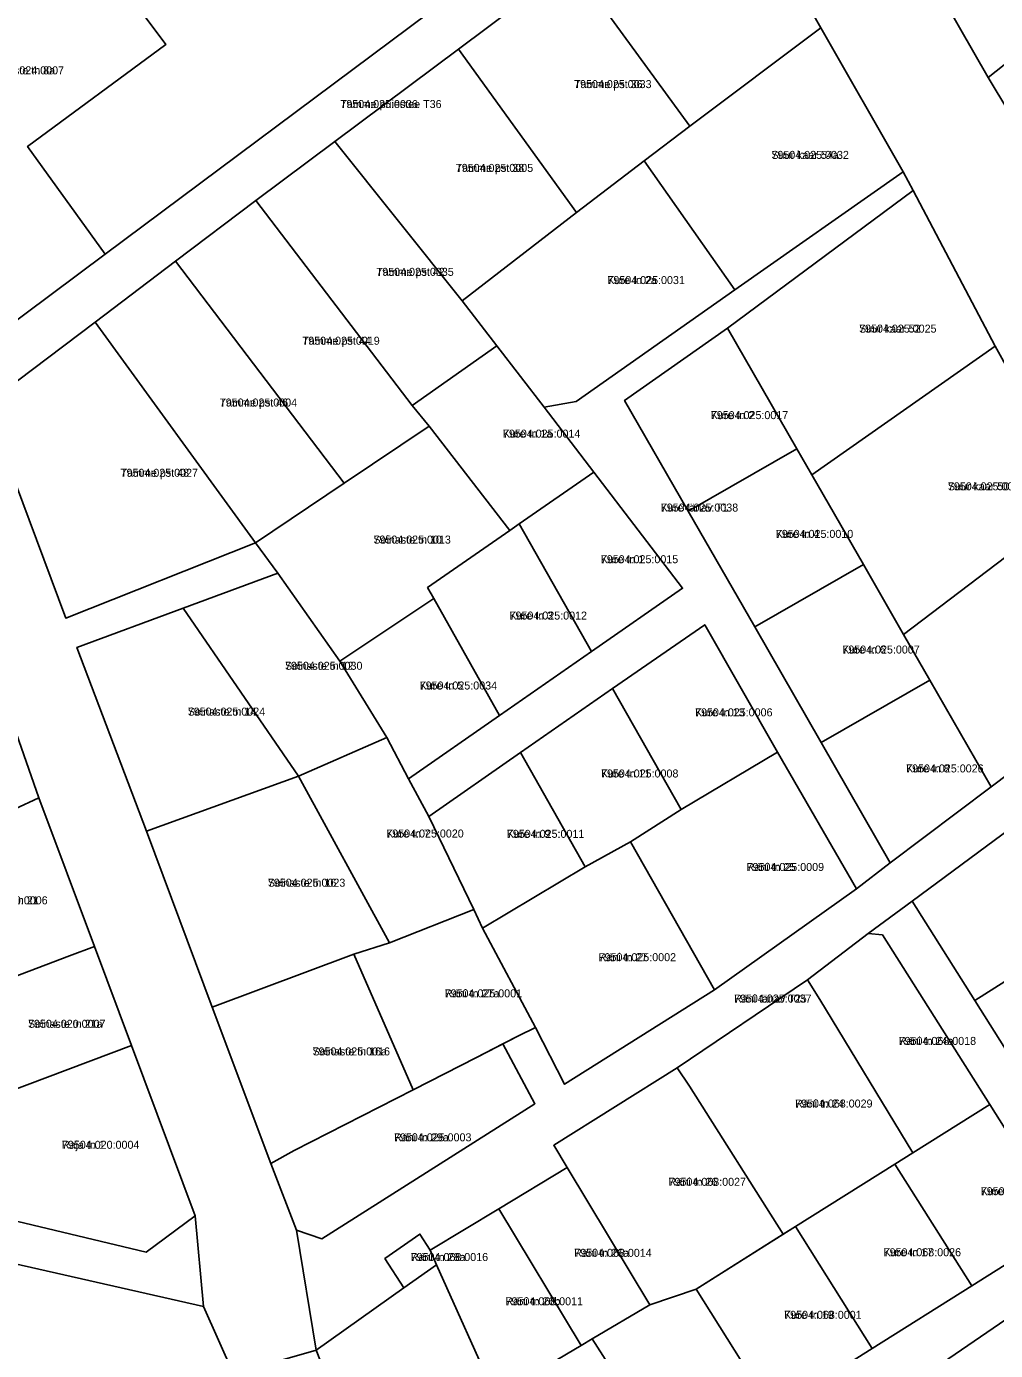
# Model space of a CAD drawing. Extents: x 643847 to 663718, y 6468443 to 6482775.
# Drawn here: x 658107 to 658288.5, y 6471992.7 to 6472240.8 of the extents above; entities that cross this region are included whole.
import ezdxf

# ---------------------------------------------------------------- set-up
doc = ezdxf.new("R2010")
doc.units = 0
for name, color, linetype in [('L_AADRESS', 7, 'Continuous'), ('PIIR', 7, 'Continuous'), ('TUNNUS', 7, 'Continuous')]:
    doc.layers.add(name, color=color, linetype=linetype)

msp = doc.modelspace()

# ---------------------------------------------------------------- linework, layer by layer
at = {"layer": 'PIIR'}
for points in [[(658324.3, 6472260.73), (658287.19, 6472231.24), (658255.18, 6472287.1), (658292.14, 6472314.34), (658310.38, 6472291.08), (658312.11, 6472278.46)], [(658096.55, 6472179.3), (658060.13, 6472228.1), (658085.61, 6472247.27), (658074.4, 6472263.34), (658118.46, 6472296.24), (658129.72, 6472280.2), (658139, 6472266.96), (658121.03, 6472253.66), (658133.15, 6472237.45), (658107.24, 6472218.32), (658121.79, 6472198.16)], [(658158.39, 6472272.98), (658182.38, 6472243.36), (658121.79, 6472198.16), (658107.24, 6472218.32), (658133.15, 6472237.45), (658121.03, 6472253.66), (658139, 6472266.96), (658129.72, 6472280.2), (658143.16, 6472291.75)], [(658209.21, 6472252.47), (658187.94, 6472236.55), (658164.81, 6472219.24), (658149.97, 6472208.2), (658134.95, 6472196.81), (658119.9, 6472185.37), (658099.41, 6472169.96), (658096.55, 6472179.3), (658121.79, 6472198.16), (658182.38, 6472243.36), (658232.79, 6472281.08), (658237.08, 6472273.31)], [(658209.21, 6472252.47), (658237.08, 6472273.31), (658255.85, 6472240.53), (658231.28, 6472222.13)], [(658187.94, 6472236.55), (658209.21, 6472252.47), (658231.28, 6472222.13), (658222.76, 6472215.62), (658210.07, 6472205.97)], [(658255.85, 6472240.53), (658271.27, 6472213.59), (658239.74, 6472191.45), (658222.76, 6472215.62), (658231.28, 6472222.13)], [(658187.94, 6472236.55), (658210.07, 6472205.97), (658188.66, 6472189.39), (658164.81, 6472219.24)], [(658149.97, 6472208.2), (658164.81, 6472219.24), (658188.66, 6472189.39), (658195.15, 6472180.94), (658179.28, 6472169.79)], [(658239.74, 6472191.45), (658209.98, 6472170.55), (658203.97, 6472169.43), (658195.15, 6472180.94), (658188.66, 6472189.39), (658210.07, 6472205.97), (658222.76, 6472215.62)], [(658271.27, 6472213.59), (658273.12, 6472210.07), (658238.37, 6472184.29), (658219.07, 6472170.73), (658230.99, 6472149.95), (658243.43, 6472128.27), (658255.87, 6472106.59), (658268.81, 6472084.03), (658262.48, 6472079.19), (658247.72, 6472104.8), (658234.07, 6472128.69), (658216.83, 6472116.7), (658199.59, 6472104.71), (658182.39, 6472092.74), (658178.57, 6472099.78), (658195.66, 6472111.68), (658212.88, 6472123.66), (658229.92, 6472135.52), (658213.28, 6472157.3), (658203.97, 6472169.43), (658209.98, 6472170.55), (658239.74, 6472191.45)], [(658288.46, 6472180.88), (658254.14, 6472156.79), (658251.35, 6472161.65), (658238.37, 6472184.29), (658273.12, 6472210.07)], [(658149.97, 6472208.2), (658179.28, 6472169.79), (658182.45, 6472165.92), (658166.56, 6472155.23), (658134.95, 6472196.81)], [(658166.56, 6472155.23), (658149.92, 6472144.03), (658119.9, 6472185.37), (658134.95, 6472196.81)], [(658119.9, 6472185.37), (658149.92, 6472144.03), (658114.38, 6472129.94), (658099.41, 6472169.96)], [(658219.07, 6472170.73), (658238.37, 6472184.29), (658251.35, 6472161.65), (658230.99, 6472149.95)], [(658199.29, 6472147.57), (658197.57, 6472146.37), (658182.45, 6472165.92), (658179.28, 6472169.79), (658195.15, 6472180.94), (658203.97, 6472169.43), (658213.28, 6472157.3)], [(658304.45, 6472152.02), (658271.32, 6472126.85), (658263.79, 6472139.96), (658254.14, 6472156.79), (658288.46, 6472180.88)], [(658166.56, 6472155.23), (658182.45, 6472165.92), (658197.57, 6472146.37), (658182.15, 6472135.63), (658183.31, 6472133.58), (658165.71, 6472121.86), (658154.14, 6472138.34), (658149.92, 6472144.03)], [(658230.99, 6472149.95), (658251.35, 6472161.65), (658254.14, 6472156.79), (658263.79, 6472139.96), (658243.43, 6472128.27)], [(658212.88, 6472123.66), (658199.29, 6472147.57), (658213.28, 6472157.3), (658229.92, 6472135.52)], [(658320.52, 6472123.03), (658287.73, 6472098.27), (658276.26, 6472118.28), (658271.32, 6472126.85), (658304.45, 6472152.02)], [(658195.66, 6472111.68), (658183.31, 6472133.58), (658182.15, 6472135.63), (658197.57, 6472146.37), (658199.29, 6472147.57), (658212.88, 6472123.66)], [(658243.43, 6472128.27), (658263.79, 6472139.96), (658271.32, 6472126.85), (658276.26, 6472118.28), (658255.87, 6472106.59)], [(658136.36, 6472131.77), (658154.14, 6472138.34), (658165.71, 6472121.86), (658174.56, 6472107.53), (658158.01, 6472100.31)], [(658195.66, 6472111.68), (658178.57, 6472099.78), (658174.56, 6472107.53), (658165.71, 6472121.86), (658183.31, 6472133.58)], [(658116.47, 6472124.42), (658136.36, 6472131.77), (658158.01, 6472100.31), (658129.49, 6472090.01)], [(658234.07, 6472128.69), (658247.72, 6472104.8), (658229.69, 6472094.04), (658216.83, 6472116.7)], [(658255.87, 6472106.59), (658276.26, 6472118.28), (658287.73, 6472098.27), (658268.81, 6472084.03)], [(658109.36, 6472096.21), (658104.82, 6472094.11), (658081.47, 6472083.26), (658078.38, 6472087.25), (658071.32, 6472096.58), (658102.78, 6472115.07)], [(658216.83, 6472116.7), (658229.69, 6472094.04), (658220.19, 6472087.98), (658211.66, 6472083.29), (658199.59, 6472104.71)], [(658174.56, 6472107.53), (658178.57, 6472099.78), (658182.39, 6472092.74), (658190.85, 6472075.29), (658175.01, 6472069.07), (658158.01, 6472100.31)], [(658235.92, 6472060.26), (658220.19, 6472087.98), (658229.69, 6472094.04), (658247.72, 6472104.8), (658262.48, 6472079.19)], [(658182.39, 6472092.74), (658199.59, 6472104.71), (658211.66, 6472083.29), (658192.47, 6472071.84), (658190.85, 6472075.29)], [(658168.36, 6472066.92), (658141.79, 6472057.03), (658129.49, 6472090.01), (658158.01, 6472100.31), (658175.01, 6472069.07)], [(658119.79, 6472068.36), (658115.12, 6472066.6), (658087.94, 6472056.34), (658085.28, 6472063.98), (658074.69, 6472078.27), (658081.47, 6472083.26), (658104.82, 6472094.11), (658109.36, 6472096.21)], [(658272.91, 6472076.89), (658291.41, 6472090.56), (658304.11, 6472070.54), (658284.64, 6472058.28)], [(658207.83, 6472042.55), (658202.35, 6472053.19), (658192.47, 6472071.84), (658211.66, 6472083.29), (658220.19, 6472087.98), (658235.92, 6472060.26)], [(658199.22, 6472051.61), (658191.3, 6472047.59), (658179.45, 6472041.53), (658168.36, 6472066.92), (658175.01, 6472069.07), (658190.85, 6472075.29), (658192.47, 6472071.84), (658202.35, 6472053.19)], [(658264.68, 6472070.81), (658267.37, 6472070.53), (658287.46, 6472038.78), (658273.07, 6472029.73), (658255.61, 6472058.41), (658253.34, 6472062.14)], [(658296.89, 6472038.82), (658284.64, 6472058.28), (658304.11, 6472070.54), (658310.39, 6472060.55), (658316.36, 6472051.07)], [(658126.71, 6472049.81), (658095.19, 6472037.92), (658087.94, 6472056.34), (658115.12, 6472066.6), (658119.79, 6472068.36)], [(658141.79, 6472057.03), (658168.36, 6472066.92), (658179.45, 6472041.53), (658157.19, 6472030.12), (658152.8, 6472027.71)], [(658228.93, 6472045.66), (658253.34, 6472062.14), (658255.61, 6472058.41), (658273.07, 6472029.73), (658269.69, 6472027.6), (658251.08, 6472015.88), (658248.79, 6472014.43), (658231.24, 6472042.19)], [(658095.19, 6472037.92), (658126.71, 6472049.81), (658138.64, 6472017.87), (658129.48, 6472011.11), (658091.01, 6472020.27)], [(658157.6, 6472015.18), (658152.8, 6472027.71), (658157.19, 6472030.12), (658179.45, 6472041.53), (658191.3, 6472047.59), (658196.25, 6472050.11), (658202.28, 6472038.89), (658162.36, 6472013.6)], [(658228.93, 6472045.66), (658231.24, 6472042.19), (658248.79, 6472014.43), (658232.47, 6472004.15), (658223.81, 6472001.23), (658208.33, 6472026.94), (658205.81, 6472031.13)], [(658284.08, 6472004.75), (658269.69, 6472027.6), (658273.07, 6472029.73), (658287.46, 6472038.78), (658301.84, 6472015.94)], [(658208.33, 6472026.94), (658223.81, 6472001.23), (658212.96, 6471994.81), (658210.9, 6471993.59), (658195.48, 6472019.19)], [(658265.46, 6471993.03), (658251.08, 6472015.88), (658269.69, 6472027.6), (658284.08, 6472004.75)], [(658195.48, 6472019.19), (658210.9, 6471993.59), (658194.89, 6471984.1), (658183.85, 6472008.74), (658182.63, 6472011.46)], [(658246.85, 6471981.3), (658232.47, 6472004.15), (658251.08, 6472015.88), (658265.46, 6471993.03)], [(658180.74, 6472014.47), (658182.63, 6472011.46), (658183.85, 6472008.74), (658177.7, 6472004.37), (658174.17, 6472009.87)], [(658140.18, 6472000.92), (658145.84, 6471988.27), (658108.85, 6471960.72), (658098.74, 6471984.59), (658098.56, 6472010.33)], [(658161.28, 6471992.71), (658177.7, 6472004.37), (658183.85, 6472008.74), (658194.89, 6471984.1), (658198.54, 6471975.94), (658172.4, 6471964.51)], [(658277.4, 6471989.53), (658306.11, 6472009.17), (658315.36, 6471997.27), (658323.4, 6471987.19), (658299.95, 6471970.14), (658295.95, 6471967.23)], [(658228.09, 6471971.22), (658212.96, 6471994.81), (658223.81, 6472001.23), (658232.47, 6472004.15), (658246.85, 6471981.3)], [(658208.99, 6471960.94), (658198.54, 6471975.94), (658194.89, 6471984.1), (658210.9, 6471993.59), (658212.96, 6471994.81), (658228.09, 6471971.22)]]:
    msp.add_lwpolyline(points, close=True, dxfattribs=at)
for points in [[(658255.18, 6472287.1), (658287.19, 6472231.24), (658291.01, 6472224.8)], [(658304.45, 6472152.02), (658288.46, 6472180.88), (658273.12, 6472210.07), (658271.27, 6472213.59), (658255.85, 6472240.53), (658237.08, 6472273.31)], [(658333.8, 6472258.8), (658305.91, 6472236.61), (658291.01, 6472224.8), (658287.19, 6472231.24), (658324.3, 6472260.73)], [(658099.41, 6472169.96), (658114.38, 6472129.94), (658149.92, 6472144.03), (658154.14, 6472138.34), (658136.36, 6472131.77), (658116.47, 6472124.42), (658129.49, 6472090.01), (658141.79, 6472057.03), (658152.8, 6472027.71), (658157.6, 6472015.18), (658161.28, 6471992.71), (658145.84, 6471988.27), (658140.18, 6472000.92), (658138.64, 6472017.87), (658126.71, 6472049.81), (658119.79, 6472068.36), (658109.36, 6472096.21), (658102.78, 6472115.07)], [(658291.41, 6472090.56), (658272.91, 6472076.89), (658264.68, 6472070.81), (658253.34, 6472062.14), (658228.93, 6472045.66), (658205.81, 6472031.13), (658208.33, 6472026.94), (658195.48, 6472019.19), (658182.63, 6472011.46), (658180.74, 6472014.47), (658174.17, 6472009.87), (658177.7, 6472004.37), (658161.28, 6471992.71), (658157.6, 6472015.18), (658162.36, 6472013.6), (658202.28, 6472038.89), (658196.25, 6472050.11), (658199.22, 6472051.61), (658202.35, 6472053.19), (658207.83, 6472042.55), (658235.92, 6472060.26), (658262.48, 6472079.19), (658268.81, 6472084.03), (658287.73, 6472098.27), (658320.52, 6472123.03)], [(658246.85, 6471981.3), (658265.46, 6471993.03), (658284.08, 6472004.75), (658301.84, 6472015.94), (658287.46, 6472038.78), (658267.37, 6472070.53), (658264.68, 6472070.81), (658272.91, 6472076.89), (658284.64, 6472058.28), (658296.89, 6472038.82), (658308.61, 6472020.2), (658320.86, 6472000.73), (658315.36, 6471997.27), (658306.11, 6472009.17), (658277.4, 6471989.53)], [(658091.01, 6472020.27), (658129.48, 6472011.11), (658138.64, 6472017.87), (658140.18, 6472000.92), (658098.56, 6472010.33)], [(658145.84, 6471988.27), (658161.28, 6471992.71), (658172.4, 6471964.51)]]:
    msp.add_lwpolyline(points, dxfattribs=at)

# ---------------------------------------------------------------- texts
at = {"layer": 'L_AADRESS'}
for s, p in [('Soinaste tn 8a', (658099.57, 6472231.84)), ('Tamme pst 36', (658209.61, 6472229.26)), ('Tamme puiestee T36', (658165.83, 6472225.52)), ('Suur kaar 54a', (658246.57, 6472215.99)), ('Tamme pst 38', (658187.44, 6472213.55)), ('Tamme pst 42', (658172.56, 6472194.07)), ('Kure tn 2a', (658215.85, 6472192.53)), ('Suur kaar 52', (658262.99, 6472183.43)), ('Tamme pst 44', (658158.7, 6472181.16)), ('Tamme pst 46', (658143.23, 6472169.58)), ('Kure tn 2', (658235.21, 6472167.22)), ('Kure tn 1a', (658196.28, 6472163.75)), ('Tamme pst 48', (658124.66, 6472156.41)), ('Suur kaar 50', (658279.62, 6472153.87)), ('Kure tänav T1', (658225.84, 6472149.89)), ('Soinaste tn 10', (658172.02, 6472143.89)), ('Kure tn 4', (658247.39, 6472144.96)), ('Kure tn 1', (658214.61, 6472140.21)), ('Kure tn 3', (658197.52, 6472129.65)), ('Kure tn 6', (658259.84, 6472123.28)), ('Soinaste tn 12', (658155.46, 6472120.24)), ('Kure tn 5', (658180.68, 6472116.54)), ('Soinaste tn 14', (658137.24, 6472111.65)), ('Kure tn 13', (658232.27, 6472111.51)), ('Kure tn 8', (658271.8, 6472101)), ('Kure tn 11', (658214.64, 6472100.05)), ('Kure tn 7', (658174.43, 6472088.8)), ('Kure tn 9', (658197.02, 6472088.74)), ('Räni tn 25', (658241.92, 6472082.53)), ('Soinaste tn 16', (658152.25, 6472079.58)), ('Soinaste tn 21', (658096.5, 6472076.28)), ('Räni tn 27', (658214.2, 6472065.62)), ('Räni tn 27a', (658185.36, 6472058.84)), ('Räni tänav T25', (658239.57, 6472057.87)), ('Soinaste tn 21a', (658107.33, 6472053.14)), ('Räni tn 24a', (658270.4, 6472049.93)), ('Soinaste tn 16a', (658160.62, 6472047.96)), ('Räni tn 24', (658251, 6472038.19)), ('Räni tn 29a', (658175.88, 6472031.86)), ('Raja tn 1', (658113.68, 6472030.46)), ('Räni tn 26', (658227.3, 6472023.52)), ('Kure tn 15', (658285.77, 6472021.76)), ('Räni tn 28a', (658179, 6472009.42)), ('Räni tn 26a', (658209.64, 6472010.21)), ('Kure tn 17', (658267.58, 6472010.32)), ('Räni tn 26b', (658196.77, 6472001.13)), ('Kure tn 19', (658248.96, 6471998.59))]:
    msp.add_text(s, height=1.5, dxfattribs=at).set_placement(p)
at = {"layer": 'TUNNUS'}
for s, p in [('79504:024:0007', (658099.57, 6472231.84)), ('79504:025:0033', (658209.61, 6472229.26)), ('79504:025:0036', (658165.83, 6472225.52)), ('79504:025:0032', (658246.57, 6472215.99)), ('79504:025:0005', (658187.44, 6472213.55)), ('79504:025:0035', (658172.56, 6472194.07)), ('79504:025:0031', (658215.85, 6472192.53)), ('79504:025:0025', (658262.99, 6472183.43)), ('79504:025:0019', (658158.7, 6472181.16)), ('79504:025:0004', (658143.23, 6472169.58)), ('79504:025:0017', (658235.21, 6472167.22)), ('79504:025:0014', (658196.28, 6472163.75)), ('79504:025:0027', (658124.66, 6472156.41)), ('79504:025:0022', (658279.62, 6472153.87)), ('79504:025:0038', (658225.84, 6472149.89)), ('79504:025:0013', (658172.02, 6472143.89)), ('79504:025:0010', (658247.39, 6472144.96)), ('79504:025:0015', (658214.61, 6472140.21)), ('79504:025:0012', (658197.52, 6472129.65)), ('79504:025:0007', (658259.84, 6472123.28)), ('79504:025:0030', (658155.46, 6472120.24)), ('79504:025:0034', (658180.68, 6472116.54)), ('79504:025:0024', (658137.24, 6472111.65)), ('79504:025:0006', (658232.27, 6472111.51)), ('79504:025:0026', (658271.8, 6472101)), ('79504:025:0008', (658214.64, 6472100.05)), ('79504:025:0020', (658174.43, 6472088.8)), ('79504:025:0011', (658197.02, 6472088.74)), ('79504:025:0009', (658241.92, 6472082.53)), ('79504:025:0023', (658152.25, 6472079.58)), ('79504:020:0006', (658096.5, 6472076.28)), ('79504:025:0002', (658214.2, 6472065.62)), ('79504:025:0001', (658185.36, 6472058.84)), ('79504:025:0037', (658239.57, 6472057.87)), ('79504:020:0007', (658107.33, 6472053.14)), ('79504:068:0018', (658270.4, 6472049.93)), ('79504:025:0016', (658160.62, 6472047.96)), ('79504:068:0029', (658251, 6472038.19)), ('79504:025:0003', (658175.88, 6472031.86)), ('79504:020:0004', (658113.68, 6472030.46)), ('79504:068:0027', (658227.3, 6472023.52)), ('79504:068:0022', (658285.77, 6472021.76)), ('79504:068:0016', (658179, 6472009.42)), ('79504:068:0014', (658209.64, 6472010.21)), ('79504:068:0026', (658267.58, 6472010.32)), ('79504:068:0011', (658196.77, 6472001.13)), ('79504:068:0001', (658248.96, 6471998.59))]:
    msp.add_text(s, height=1.5, dxfattribs=at).set_placement(p)

doc.saveas('drawing.dxf')
